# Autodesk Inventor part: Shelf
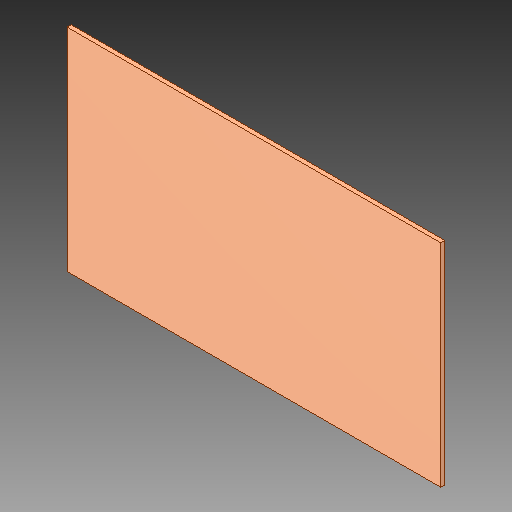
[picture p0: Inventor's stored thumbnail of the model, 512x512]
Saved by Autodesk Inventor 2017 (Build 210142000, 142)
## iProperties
Created: 2017-05
Part Number: Shelf
Material: Generic
Document SubType Name: Modeling
Designer: Savy
Density: 1 g/cm^3
Appearance: Default
Author: Savy
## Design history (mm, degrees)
feature "SOLID1"
body "Solid1"
